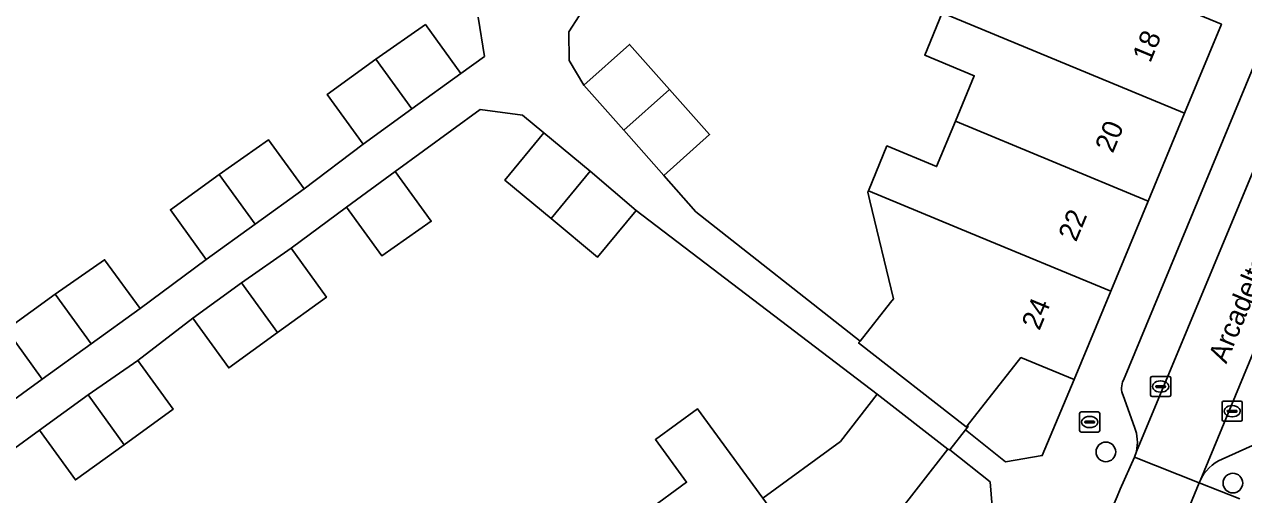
# Model space of a CAD drawing. Extents: x 159817 to 160765, y 380688 to 381638.
# Drawn here: x 159990.7 to 160051.4, y 381351.6 to 381374.9 of the extents above; entities that cross this region are included whole.
import ezdxf

# ---------------------------------------------------------------- set-up
doc = ezdxf.new("R2010")
doc.units = 0
for name, color, linetype in [('IMGEO_Boom', 7, 'Continuous'), ('IMGEO_Brandkraan', 7, 'Continuous'), ('IMGEO_Erf', 7, 'Continuous'), ('IMGEO_Kolk', 7, 'Continuous'), ('IMGEO_Openbare_ruimte_label', 7, 'Continuous'), ('IMGEO_Pand', 7, 'Continuous'), ('IMGEO_Pand_nummerreeks', 7, 'Continuous'), ('IMGEO_Parkeervlak_open', 7, 'Continuous'), ('IMGEO_Rijbaan_lokaal_open', 7, 'Continuous'), ('IMGEO_Voetpad_open', 7, 'Continuous')]:
    doc.layers.add(name, color=color, linetype=linetype)

msp = doc.modelspace()

# ---------------------------------------------------------------- linework, layer by layer
at = {"layer": 'IMGEO_Boom'}
for centre in [(160044.532, 381353.695), (160050.849, 381352.14)]:
    msp.add_circle(centre, 0.489, dxfattribs=at)
at = {"layer": 'IMGEO_Brandkraan'}
for p, q in [((160043.227, 381354.752), (160043.227, 381355.604)), ((160043.302, 381355.678), (160044.154, 381355.678)), ((160044.228, 381355.604), (160044.228, 381354.752)), ((160043.486, 381355.172), (160043.486, 381355.184)), ((160043.924, 381355.135), (160043.526, 381355.135)), ((160043.529, 381355.221), (160043.927, 381355.221)), ((160043.715, 381355.458), (160043.74, 381355.458)), ((160043.97, 381355.184), (160043.97, 381355.172)), ((160044.154, 381354.678), (160043.302, 381354.678)), ((160043.738, 381354.898), (160043.713, 381354.898))]:
    msp.add_line(p, q, dxfattribs=at)
for points in [[(160043.227, 381354.752), (160043.227, 381355.604)], [(160043.302, 381355.678), (160044.154, 381355.678)], [(160044.228, 381355.604), (160044.228, 381354.752)], [(160044.154, 381354.678), (160043.302, 381354.678)]]:
    msp.add_lwpolyline(points, dxfattribs=at)
for centre, radius, start, end in [((160043.304, 381355.602), 0.0765, 91.55205, 178.44795), ((160043.304, 381355.602), 0.0765, 91.55205, 178.44795), ((160044.152, 381355.602), 0.0765, 1.55205, 88.44795), ((160044.152, 381355.602), 0.0765, 1.55205, 88.44795), ((160043.526, 381355.181), 0.0403, 85.87752, 175.75265), ((160043.523, 381355.171), 0.0366, 178.93798, 274.71019), ((160043.927, 381355.178), 0.043, 264.86636, 352.45326), ((160043.931, 381355.183), 0.0386, 1.73085, 96.63898), ((160043.304, 381354.754), 0.0765, 181.55205, 268.44795), ((160043.304, 381354.754), 0.0765, 181.55205, 268.44795), ((160044.152, 381354.754), 0.0765, 271.55205, 358.44795), ((160044.152, 381354.754), 0.0765, 271.55205, 358.44795)]:
    msp.add_arc(centre, radius, start, end, dxfattribs=at)
for centre, major_axis, ratio, start_param, end_param in [((160043.714, 381355.178), (-0.387, 0.002), 0.722429, 4.712389, 7.853982), ((160043.739, 381355.178), (-0.39, 0.002), 0.717154, 1.570796, 4.712389)]:
    msp.add_ellipse(centre, major_axis=major_axis, ratio=ratio, start_param=start_param, end_param=end_param, dxfattribs=at)
at = {"layer": 'IMGEO_Erf'}
for points in [[(160020.905, 381379.37), (160017.829, 381374.578), (160017.846, 381373.155), (160018.563, 381371.926), (160020.844, 381373.95), (160022.832, 381371.708), (160024.82, 381369.466), (160022.544, 381367.437), (160024.14, 381365.636), (160032.306, 381359.201), (160033.824, 381361.127), (160033.967, 381361.308), (160032.797, 381366.171), (160032.693, 381366.604), (160032.723, 381366.677), (160033.645, 381368.903), (160036.117, 381367.879), (160037.052, 381370.135), (160037.987, 381372.392), (160035.525, 381373.411), (160036.399, 381375.522)], [(159987.515, 381354.32), (159991.634, 381357.302), (159989.846, 381359.773), (159992.273, 381361.53), (159994.736, 381363.25), (159996.495, 381360.819), (159999.791, 381363.259), (159998.003, 381365.73), (160000.43, 381367.487), (160002.893, 381369.207), (160004.652, 381366.776), (160007.59, 381368.991), (160005.803, 381371.462), (160008.23, 381373.219), (160010.693, 381374.939), (160012.451, 381372.508), (160013.627, 381373.359), (160013.312, 381375.313)], [(160021.732, 381350.755), (160023.683, 381352.18), (160022.128, 381354.309), (160024.219, 381355.836), (160027.467, 381351.387), (160031.335, 381354.211), (160033.164, 381356.557), (160021.165, 381365.687), (160019.25, 381363.379), (160016.938, 381365.297), (160014.632, 381367.211), (160016.58, 381369.557), (160015.517, 381370.439), (160013.408, 381370.709), (160009.185, 381367.626), (160010.983, 381365.163), (160008.53, 381363.434), (160006.762, 381365.857), (160004.011, 381363.815), (160005.769, 381361.385), (160003.336, 381359.624), (160000.908, 381357.868), (159999.121, 381360.339), (159996.382, 381358.244), (159998.14, 381355.813), (159995.707, 381354.052), (159993.279, 381352.296), (159991.492, 381354.768), (159988.668, 381352.726)]]:
    msp.add_lwpolyline(points, dxfattribs=at)
for points in [[(160042.959, 381357.286), (160040.309, 381358.383), (160037.639, 381354.996), (160037.681, 381354.963), (160037.549, 381354.798), (160039.548, 381353.205), (160041.373, 381353.509)], [(160038.773, 381352.204), (160036.769, 381353.793), (160036.671, 381353.824), (160033.991, 381350.384), (160035.667, 381348.09), (160038.934, 381350.359)]]:
    msp.add_lwpolyline(points, close=True, dxfattribs=at)
at = {"layer": 'IMGEO_Kolk'}
for p, q in [((160046.832, 381357.442), (160047.684, 381357.442)), ((160046.757, 381356.516), (160046.757, 381357.368)), ((160047.016, 381356.936), (160047.016, 381356.948)), ((160047.454, 381356.899), (160047.056, 381356.899)), ((160047.059, 381356.985), (160047.457, 381356.985)), ((160047.245, 381357.222), (160047.27, 381357.222)), ((160047.5, 381356.948), (160047.5, 381356.936)), ((160047.758, 381357.368), (160047.758, 381356.516)), ((160047.684, 381356.442), (160046.832, 381356.442)), ((160047.268, 381356.662), (160047.243, 381356.662)), ((160050.391, 381356.216), (160051.243, 381356.216)), ((160050.316, 381355.29), (160050.316, 381356.142)), ((160050.575, 381355.71), (160050.575, 381355.722)), ((160051.013, 381355.673), (160050.615, 381355.673)), ((160050.618, 381355.759), (160051.016, 381355.759)), ((160050.804, 381355.996), (160050.829, 381355.996)), ((160051.059, 381355.722), (160051.059, 381355.71)), ((160051.317, 381356.142), (160051.317, 381355.29)), ((160051.243, 381355.216), (160050.391, 381355.216)), ((160050.827, 381355.436), (160050.802, 381355.436))]:
    msp.add_line(p, q, dxfattribs=at)
for points in [[(160046.832, 381357.442), (160047.684, 381357.442)], [(160046.757, 381356.516), (160046.757, 381357.368)], [(160047.758, 381357.368), (160047.758, 381356.516)], [(160047.684, 381356.442), (160046.832, 381356.442)], [(160050.391, 381356.216), (160051.243, 381356.216)], [(160050.316, 381355.29), (160050.316, 381356.142)], [(160051.317, 381356.142), (160051.317, 381355.29)], [(160051.243, 381355.216), (160050.391, 381355.216)]]:
    msp.add_lwpolyline(points, dxfattribs=at)
for centre, radius, start, end in [((160046.834, 381357.366), 0.0765, 91.55205, 178.44795), ((160046.834, 381357.366), 0.0765, 91.55205, 178.44795), ((160047.682, 381357.366), 0.0765, 1.55205, 88.44795), ((160047.682, 381357.366), 0.0765, 1.55205, 88.44795), ((160047.056, 381356.945), 0.0403, 85.87752, 175.75265), ((160047.053, 381356.935), 0.0366, 178.93798, 274.71019), ((160047.457, 381356.942), 0.043, 264.86636, 352.45326), ((160047.461, 381356.947), 0.0386, 1.73085, 96.63898), ((160046.834, 381356.518), 0.0765, 181.55205, 268.44795), ((160046.834, 381356.518), 0.0765, 181.55205, 268.44795), ((160047.682, 381356.518), 0.0765, 271.55205, 358.44795), ((160047.682, 381356.518), 0.0765, 271.55205, 358.44795), ((160050.393, 381356.14), 0.0765, 91.55205, 178.44795), ((160050.393, 381356.14), 0.0765, 91.55205, 178.44795), ((160051.241, 381356.14), 0.0765, 1.55205, 88.44795), ((160051.241, 381356.14), 0.0765, 1.55205, 88.44795), ((160050.615, 381355.719), 0.0403, 85.87752, 175.75265), ((160050.612, 381355.709), 0.0366, 178.93798, 274.71019), ((160051.016, 381355.716), 0.043, 264.86636, 352.45326), ((160051.02, 381355.721), 0.0386, 1.73085, 96.63898), ((160050.393, 381355.292), 0.0765, 181.55205, 268.44795), ((160050.393, 381355.292), 0.0765, 181.55205, 268.44795), ((160051.241, 381355.292), 0.0765, 271.55205, 358.44795), ((160051.241, 381355.292), 0.0765, 271.55205, 358.44795)]:
    msp.add_arc(centre, radius, start, end, dxfattribs=at)
for centre, major_axis, ratio, start_param, end_param in [((160047.244, 381356.942), (-0.387, 0.002), 0.722429, 4.712389, 7.853982), ((160047.269, 381356.942), (-0.39, 0.002), 0.717154, 1.570796, 4.712389), ((160050.803, 381355.716), (-0.387, 0.002), 0.722429, 4.712389, 7.853982), ((160050.828, 381355.716), (-0.39, 0.002), 0.717154, 1.570796, 4.712389)]:
    msp.add_ellipse(centre, major_axis=major_axis, ratio=ratio, start_param=start_param, end_param=end_param, dxfattribs=at)
at = {"layer": 'IMGEO_Pand'}
for points in [[(160036.399, 381375.522), (160048.446, 381370.533), (160050.279, 381374.957), (160040.736, 381378.909), (160039.779, 381376.597), (160037.274, 381377.634)], [(160036.399, 381375.522), (160035.525, 381373.411), (160037.987, 381372.392), (160037.052, 381370.135), (160046.637, 381366.164), (160048.446, 381370.533)], [(160008.23, 381373.219), (160010.018, 381370.748), (160012.451, 381372.508), (160010.693, 381374.939)], [(160020.551, 381369.685), (160022.832, 381371.708), (160020.844, 381373.95), (160018.563, 381371.926)], [(160008.23, 381373.219), (160005.803, 381371.462), (160007.59, 381368.991), (160010.018, 381370.748)], [(160020.551, 381369.685), (160022.544, 381367.437), (160024.82, 381369.466), (160022.832, 381371.708)], [(160018.886, 381367.644), (160016.58, 381369.557), (160014.632, 381367.211), (160016.938, 381365.297)], [(160037.8, 381364.574), (160044.78, 381361.683), (160046.637, 381366.164), (160037.052, 381370.135), (160036.117, 381367.879), (160033.645, 381368.903), (160032.723, 381366.677)], [(160002.218, 381365.015), (160004.652, 381366.776), (160002.893, 381369.207), (160000.43, 381367.487)], [(160002.218, 381365.015), (160000.43, 381367.487), (159998.003, 381365.73), (159999.791, 381363.259)], [(160008.53, 381363.434), (160010.983, 381365.163), (160009.185, 381367.626), (160006.762, 381365.857)], [(160018.886, 381367.644), (160016.938, 381365.297), (160019.25, 381363.379), (160021.165, 381365.687)], [(160044.78, 381361.683), (160037.8, 381364.574), (160032.723, 381366.677), (160032.693, 381366.604), (160032.797, 381366.171), (160033.967, 381361.308), (160033.824, 381361.127), (160032.306, 381359.201), (160032.237, 381359.114), (160037.591, 381354.935), (160037.639, 381354.996), (160040.309, 381358.383), (160042.959, 381357.286)], [(160003.336, 381359.624), (160005.769, 381361.385), (160004.011, 381363.815), (160001.548, 381362.095)], [(159992.273, 381361.53), (159994.061, 381359.058), (159996.495, 381360.819), (159994.736, 381363.25)], [(160003.336, 381359.624), (160001.548, 381362.095), (159999.121, 381360.339), (160000.908, 381357.868)], [(159992.273, 381361.53), (159989.846, 381359.773), (159991.634, 381357.302), (159994.061, 381359.058)], [(159993.919, 381356.524), (159995.707, 381354.052), (159998.14, 381355.813), (159996.382, 381358.244)], [(159993.919, 381356.524), (159991.492, 381354.768), (159993.279, 381352.296), (159995.707, 381354.052)], [(160031.888, 381345.331), (160035.667, 381348.09), (160033.991, 381350.384), (160036.671, 381353.824), (160033.164, 381356.557), (160031.335, 381354.211), (160027.467, 381351.387)], [(160031.888, 381345.331), (160027.467, 381351.387), (160024.219, 381355.836), (160022.128, 381354.309), (160023.683, 381352.18), (160021.732, 381350.755), (160027.848, 381342.381)]]:
    msp.add_lwpolyline(points, close=True, dxfattribs=at)
at = {"layer": 'IMGEO_Parkeervlak_open'}
for points in [[(160058.135, 381384.019), (160056.734, 381384.568), (160045.408, 381357.267)], [(160046.049, 381353.712), (160058.74, 381384.186)], [(160061.916, 381382.928), (160049.223, 381352.25)], [(160045.398, 381356.491), (160045.965, 381354.915)], [(160050.324, 381353.327), (160051.83, 381354.015)], [(160051.204, 381351.366), (160049.167, 381352.154), (160048.471, 381350.471)]]:
    msp.add_lwpolyline(points, dxfattribs=at)
for centre, radius, start, end in [((160046.204, 381356.869), 0.89, 153.42402, 205.09937), ((160044.019, 381354.175), 2.082, 347.15729, 20.83115), ((160051.071, 381351.462), 2.009, 111.83019, 156.90714)]:
    msp.add_arc(centre, radius, start, end, dxfattribs=at)
at = {"layer": 'IMGEO_Rijbaan_lokaal_open'}
msp.add_lwpolyline([(160077.626, 381420.841), (160078.049, 381421.832), (160078.915, 381423.919), (160075.79, 381425.372), (160074.503, 381422.274), (160074.066, 381421.231), (160059.378, 381385.649), (160058.74, 381384.186), (160046.049, 381353.712), (160045.961, 381353.423), (160049.167, 381352.154), (160049.223, 381352.25), (160061.916, 381382.928), (160063.095, 381385.76), (160063.195, 381385.942)], close=True, dxfattribs=at)
msp.add_lwpolyline([(160048.471, 381350.471), (160049.167, 381352.154), (160045.961, 381353.423), (160045.241, 381351.841)], dxfattribs=at)
msp.add_arc((160036.163, 381355.164), 9.667, 303.56654, 339.89476, dxfattribs=at)
at = {"layer": 'IMGEO_Voetpad_open'}
for points in [[(160045.408, 381357.267), (160056.734, 381384.568), (160058.135, 381384.019)], [(159988.668, 381352.726), (159991.492, 381354.768), (159993.919, 381356.524), (159996.382, 381358.244), (159999.121, 381360.339), (160001.548, 381362.095), (160004.011, 381363.815), (160006.762, 381365.857), (160009.185, 381367.626), (160013.408, 381370.709), (160015.517, 381370.439), (160016.58, 381369.557), (160018.886, 381367.644), (160021.165, 381365.687), (160033.164, 381356.557), (160036.671, 381353.824), (160036.769, 381353.793), (160037.549, 381354.798), (160037.681, 381354.963), (160037.639, 381354.996), (160037.591, 381354.935), (160032.237, 381359.114), (160032.306, 381359.201), (160024.14, 381365.636), (160022.544, 381367.437), (160020.551, 381369.685), (160018.563, 381371.926), (160017.846, 381373.155), (160017.829, 381374.578), (160020.905, 381379.37)], [(160013.312, 381375.313), (160013.627, 381373.359), (160012.451, 381372.508), (160010.018, 381370.748), (160007.59, 381368.991), (160004.652, 381366.776), (160002.218, 381365.015), (159999.791, 381363.259), (159996.495, 381360.819), (159994.061, 381359.058), (159991.634, 381357.302), (159987.515, 381354.32)], [(160050.279, 381374.957), (160048.446, 381370.533), (160046.637, 381366.164), (160044.78, 381361.683), (160042.959, 381357.286), (160041.373, 381353.509), (160039.548, 381353.205), (160037.549, 381354.798), (160036.769, 381353.793), (160038.773, 381352.204), (160038.934, 381350.359)], [(160045.965, 381354.915), (160045.398, 381356.491)], [(160051.83, 381354.015), (160050.324, 381353.327)], [(160045.241, 381351.841), (160045.961, 381353.423), (160046.049, 381353.712)], [(160049.223, 381352.25), (160049.167, 381352.154), (160051.204, 381351.366)]]:
    msp.add_lwpolyline(points, dxfattribs=at)
for centre, radius, start, end in [((160046.204, 381356.869), 0.89, 153.42402, 205.09937), ((160044.019, 381354.175), 2.082, 347.15729, 20.83115), ((160051.071, 381351.462), 2.009, 111.83019, 156.90714), ((160036.163, 381355.164), 9.667, 303.56654, 339.89476)]:
    msp.add_arc(centre, radius, start, end, dxfattribs=at)

# ---------------------------------------------------------------- texts
at = {"layer": 'IMGEO_Openbare_ruimte_label'}
msp.add_text('Arcadeltstraat', height=1, rotation=67.411, dxfattribs=at).set_placement((160050.522, 381358.039))
at = {"layer": 'IMGEO_Pand_nummerreeks'}
for s, rotation, p in [('18', 67.49926, (160046.739, 381372.997)), ('20', 67.49926, (160044.879, 381368.506)), ('22', 67.49926, (160043.052, 381364.094)), ('24', 67.50016, (160041.227, 381359.69))]:
    msp.add_text(s, height=1, rotation=rotation, dxfattribs=at).set_placement(p)

doc.saveas('drawing.dxf')
